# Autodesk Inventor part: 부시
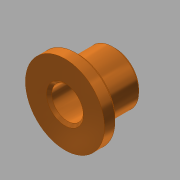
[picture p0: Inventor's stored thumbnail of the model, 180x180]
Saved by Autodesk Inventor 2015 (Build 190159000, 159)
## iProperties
Created: 2016-02
Part Number: 부시
Material: 스테인리스강
Document SubType Name: Modeling
Designer: mduedu
Density: 8.08 g/cm^3
Appearance: 금속 1600F 열
Author: mduedu
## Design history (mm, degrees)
sketch "스케치1"
  geometry: C1 r 15 at (0, 0); 1 further point
  constraints: 1 centre point, 1 coincident
  dimensions: "d0" = 30 diameter of C1
extrude "돌출1" new body sketch "스케치1" distance "d1" = 5; taper "d2" = 0 deg
sketch "스케치2"
  geometry: C1 r 10 at (0, 0); 1 further point
  constraints: 1 centre point, 1 coincident
  dimensions: "d3" = 20 diameter of C1
extrude "돌출2" join sketch "스케치2" distance "d4" = 14; taper "d5" = 0 deg
hole "구멍1" diameter "d8" = 12; stored, may be unused: countersink angle "d12" = 90 deg, drill point angle "d14" = 118 deg; dims "d9" = 6, "d10" = 4, "d11" = 2, "d13" = 8, "d15" = 10, "d16" = 10
chamfer "모따기1" distance "d17" = 1; stored, may be unused: second distance "d18" = 2, angle "d19" = 45 deg
chamfer "모따기2" distance "d20" = 1; stored, may be unused: second distance "d21" = 2, angle "d22" = 45 deg
chamfer "모따기3" distance "d23" = 1; stored, may be unused: second distance "d24" = 2, angle "d25" = 45 deg
node "솔리드1"
